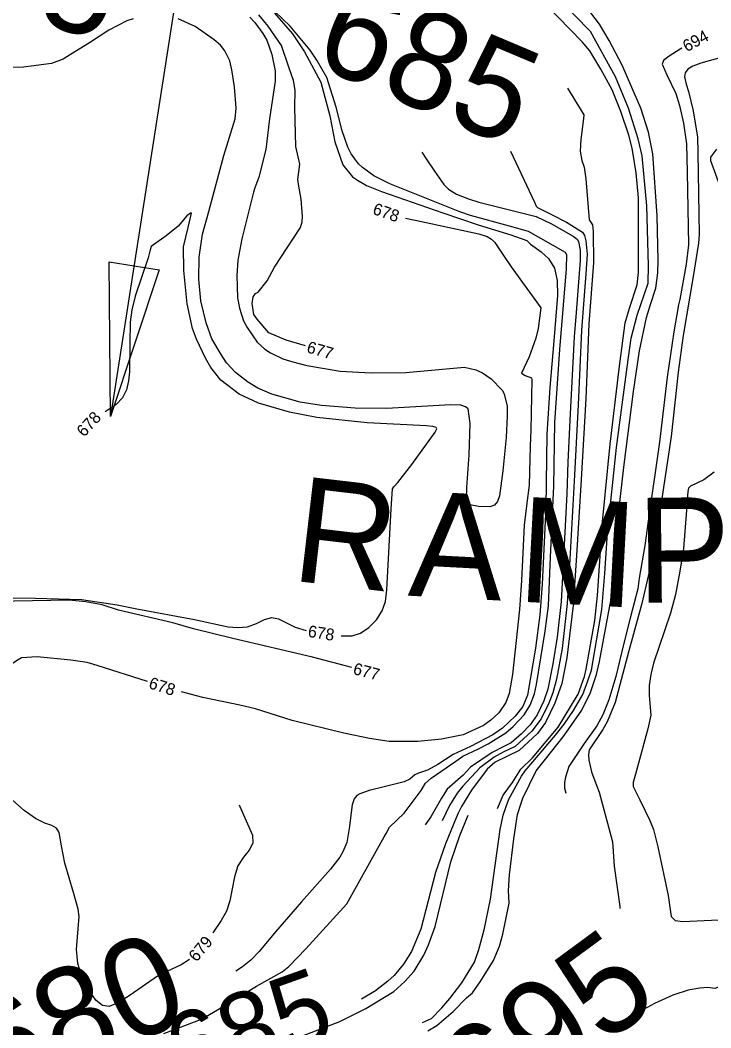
# Model space of a CAD drawing. Extents: x -291892836 to 2945206, y -477993085 to 1832792.
# Drawn here: x 1851493.5 to 1851727.1, y 544238.1 to 544578.8 of the extents above; entities that cross this region are included whole.
import ezdxf

# ---------------------------------------------------------------- set-up
doc = ezdxf.new("R2010")
doc.units = 0
for name, color, linetype in [('DT_X_Contour_Minor', 7, 'Continuous'), ('DT_X_Terrain_Ground_Line', 7, 'Continuous'), ('Level 19', 7, 'Continuous'), ('Level 40', 7, 'Continuous')]:
    doc.layers.add(name, color=color, linetype=linetype)

msp = doc.modelspace()

# ---------------------------------------------------------------- linework, layer by layer
at = {"layer": 'DT_X_Contour_Minor'}
for points in [[(1851531.68, 544579.29), (1851529.6, 544578.6), (1851523.46, 544575.49), (1851517, 544571.2), (1851510.54, 544567.23), (1851508.07, 544565.62), (1851504.12, 544564.17), (1851494.6, 544562.93), (1851490.63, 544562.85), (1851483.62, 544563.35), (1851477.39, 544564.65), (1851474.87, 544565.59), (1851472.41, 544566.76), (1851469.85, 544568.81), (1851466.75, 544571.69), (1851463.85, 544575.55), (1851462.39, 544578.37), (1851461, 544581.54), (1851456.81, 544594.48), (1851454.94, 544602.3), (1851452.23, 544617.54), (1851451.53, 544626.35), (1851451.1, 544641.26)], [(1851617.23, 544303.84), (1851618.4, 544305.96), (1851623.32, 544310.69), (1851629.13, 544318.42), (1851630.58, 544320.9), (1851632.5, 544322.48), (1851640.88, 544328.24), (1851643.22, 544329.96), (1851648.52, 544332.42), (1851651.73, 544334.17), (1851657.73, 544337.84), (1851660.25, 544340.04), (1851663.92, 544344), (1851665.98, 544347.19), (1851667.46, 544351.07), (1851668.1, 544354.21), (1851671.07, 544372.2), (1851672.12, 544380.82), (1851672.89, 544397.28), (1851673.94, 544421.24), (1851674.35, 544442.82), (1851676, 544467.43), (1851678.21, 544494.75), (1851678.38, 544499.48), (1851677.97, 544500.24), (1851665.44, 544507.33), (1851658.98, 544509.22), (1851645.75, 544512.78), (1851642.14, 544513.99), (1851618.52, 544523.49), (1851613.09, 544526.22), (1851609.27, 544529.01), (1851607.92, 544530.29), (1851605.47, 544533.58), (1851604.35, 544535.92), (1851602.37, 544541.41), (1851600.35, 544549.45), (1851597.19, 544559.47), (1851593.79, 544565.35), (1851591.56, 544568.67), (1851584.83, 544576.83), (1851574.41, 544586.83)], [(1851657.9, 544312.96), (1851658.81, 544315.45), (1851663.08, 544323.19), (1851664.28, 544325.01), (1851674.57, 544337.13), (1851677.49, 544340.83), (1851680.68, 544345.4), (1851683.77, 544350.83), (1851685.52, 544355.39), (1851686.66, 544359.01), (1851690.25, 544379.61), (1851691.17, 544391.79), (1851692.09, 544405.45), (1851695.17, 544434.29), (1851698.73, 544461.55), (1851700.17, 544471.32), (1851702.12, 544479.08), (1851705.84, 544489.86), (1851705.94, 544495.86), (1851705.37, 544516.06), (1851703.83, 544532.99), (1851702.48, 544538.7), (1851699.24, 544549.12), (1851694.85, 544559.67), (1851686.41, 544574.95), (1851675.39, 544586.26)], [(1851654.96, 544312.3), (1851656.82, 544316.8), (1851659.97, 544321.06), (1851662.8, 544325.53), (1851666.71, 544329.37), (1851675.44, 544339.78), (1851682.17, 544350.99), (1851684.32, 544356.88), (1851684.95, 544359.44), (1851687.83, 544375.83), (1851688.73, 544384.28), (1851690.47, 544409.19), (1851693, 544435.45), (1851696.02, 544460.97), (1851698.1, 544476.5), (1851699.57, 544481.42), (1851702.21, 544489.3), (1851702.6, 544493.49), (1851702.59, 544518.76), (1851701.84, 544527.19), (1851700.5, 544535.56), (1851699.39, 544539.89), (1851696.66, 544547.94), (1851693.69, 544555.28), (1851689.87, 544562.31), (1851686.17, 544568.5), (1851683.61, 544571.48), (1851671.39, 544584.03)], [(1851662.89, 544314.07), (1851663.44, 544315.8), (1851668.06, 544324.98), (1851671.2, 544329), (1851677.15, 544336.48), (1851679, 544339.22), (1851683.4, 544345.56), (1851686.33, 544351.53), (1851688.45, 544357.57), (1851689.43, 544362.02), (1851693.25, 544382.58), (1851693.94, 544391.7), (1851694.73, 544401.86), (1851697.69, 544427.67), (1851700.91, 544453.29), (1851702.97, 544467.04), (1851705.26, 544478.31), (1851706.66, 544482.7), (1851708.51, 544488.19), (1851709.13, 544493.38), (1851709.31, 544497.51), (1851708.95, 544512.69), (1851707.46, 544533.67), (1851705.99, 544540.94), (1851703.35, 544549.11), (1851700.41, 544556.05), (1851697.12, 544563.57), (1851692.72, 544571.93), (1851689.38, 544577.42), (1851685.36, 544582.82)], [(1851571.16, 544579.86), (1851572.9, 544578.01), (1851575.55, 544574.36), (1851576.92, 544572.06), (1851578.64, 544567.24), (1851579.78, 544561.69), (1851579.7, 544558.2), (1851577.85, 544545.41), (1851576.63, 544535.06), (1851574.24, 544525.76), (1851572.91, 544522.16), (1851572.43, 544520.71), (1851568.52, 544504.91), (1851567.18, 544497.67), (1851566.76, 544492.47), (1851567.02, 544484.96), (1851567.73, 544481.43), (1851569.03, 544477.2), (1851570.28, 544474.96), (1851573.69, 544469.98), (1851576.28, 544467.59), (1851578.22, 544466.39), (1851582.3, 544464.34), (1851585.67, 544463.25), (1851590.44, 544462.06), (1851601.7, 544460.15), (1851612.22, 544459.54), (1851623.94, 544459.74), (1851643.81, 544461.46), (1851647.58, 544460.64), (1851649.82, 544459.6), (1851652.8, 544457.55), (1851656.55, 544453.68), (1851657.18, 544452.52), (1851658.24, 544448.32), (1851658.25, 544444.98), (1851657.86, 544437.77), (1851656.77, 544426.42), (1851655.59, 544418), (1851654.98, 544416.07), (1851653.94, 544414.82), (1851652.33, 544414.27), (1851648.45, 544414.36), (1851645.55, 544414.91), (1851644.75, 544415.69), (1851644.41, 544417), (1851644.58, 544420.79), (1851645.32, 544431.82), (1851645.66, 544442.41), (1851645.01, 544447.38), (1851644.1, 544448.11), (1851642.57, 544448.7), (1851639.1, 544448.79), (1851617.38, 544447.51), (1851606.84, 544447.67), (1851595.38, 544448.58), (1851588.2, 544449.63), (1851578.58, 544452.33), (1851573.86, 544454.41), (1851570.35, 544456.59), (1851566.34, 544459.69), (1851563.3, 544463.02), (1851561.46, 544465.81), (1851558.35, 544471.13), (1851556.38, 544476.45), (1851554.66, 544483.89), (1851553.96, 544491.25), (1851554.1, 544498.71), (1851555.22, 544506.44), (1851557.3, 544514.16), (1851562.4, 544533.07), (1851566.24, 544545.45), (1851566.57, 544549.02), (1851565.97, 544556.25), (1851565.09, 544562.03), (1851564.45, 544565.09), (1851562.7, 544568.5), (1851561.27, 544570.39), (1851559.13, 544572.21), (1851552.69, 544576.64), (1851546.94, 544579.28)], [(1851589.99, 544468.69), (1851583.44, 544470.59), (1851577.6, 544473.15), (1851573.69, 544477.73), (1851572.48, 544479.31), (1851571.96, 544483.02), (1851572.34, 544485.25), (1851573.08, 544486.37), (1851574.04, 544486.81), (1851577, 544490.64), (1851579.55, 544495.33), (1851588.28, 544508.7), (1851588.91, 544510.66), (1851589.03, 544512.52), (1851588.59, 544518.25), (1851587.77, 544522.66), (1851587.37, 544524.94), (1851588.05, 544530.13), (1851586.72, 544536.09), (1851586.4, 544549.28), (1851586.54, 544555.18), (1851586, 544558.44), (1851584.45, 544562.58), (1851581.84, 544570.3), (1851577.39, 544576.81), (1851574.26, 544580.61)], [(1851579.49, 544581.23), (1851585.56, 544574.15), (1851589.62, 544568.13), (1851595.19, 544557.87), (1851598.27, 544546.45), (1851599.88, 544537.69), (1851602.67, 544529.94), (1851605.89, 544525.87), (1851607.56, 544524.69), (1851610.6, 544522.97), (1851615.66, 544520.86), (1851636.49, 544513.69), (1851648.39, 544509.66), (1851659.43, 544506.23), (1851664.85, 544504.3), (1851666.04, 544503.08), (1851669.68, 544500.52), (1851672.17, 544498.24), (1851674.15, 544495.01), (1851675.08, 544490.75), (1851675.17, 544485.74), (1851673.95, 544470.46), (1851672.62, 544454.65), (1851671.61, 544438.82), (1851671.25, 544414.2), (1851670.03, 544388.16), (1851669.28, 544377.74), (1851667.82, 544366.52), (1851665.05, 544350.62), (1851663.46, 544346.82), (1851660.93, 544343.51), (1851656.57, 544339.48), (1851653.38, 544337.19), (1851645.85, 544333.24), (1851639.96, 544330.57), (1851634.71, 544327.13), (1851631.21, 544325.22), (1851628.23, 544324.2), (1851627.03, 544323.65), (1851625.28, 544322.19), (1851623.39, 544321.31), (1851617.1, 544319.73), (1851611.48, 544318.42), (1851608.39, 544317.29), (1851607.31, 544316.66), (1851606.45, 544315.55), (1851605.77, 544313.48), (1851604.87, 544306.43)], [(1851717.29, 544569.33), (1851716.66, 544568.99), (1851712.96, 544566.71), (1851711.02, 544565.16), (1851710.59, 544563.95), (1851712.22, 544560.35), (1851715.25, 544554.08), (1851716.5, 544549.96), (1851717.79, 544543.96), (1851718.81, 544537.03), (1851719.09, 544527.48), (1851719.51, 544502.84), (1851718.72, 544496.33), (1851716.56, 544484.33), (1851716.08, 544482.63), (1851714.57, 544473.43), (1851712.25, 544458.16), (1851709.72, 544436.19), (1851705.85, 544409.41), (1851704.75, 544401.26), (1851702.8, 544390.15), (1851702.38, 544386.5), (1851699.89, 544377.05), (1851697.59, 544367.74), (1851694.91, 544356.89), (1851692.6, 544349), (1851690.56, 544344), (1851688.55, 544340.24), (1851684.26, 544334.31), (1851679.03, 544326.45), (1851677.95, 544322.91), (1851677.54, 544321.08), (1851677.64, 544319.1), (1851678, 544317.46)], [(1851731.3, 544566.47), (1851723.68, 544564.32), (1851720.99, 544563.27), (1851719.26, 544562.23), (1851718.36, 544561.05), (1851718.17, 544559.68), (1851718.75, 544557.2), (1851719.57, 544554.66), (1851721.11, 544548.13), (1851722.52, 544539.24), (1851722.72, 544533.95), (1851723.1, 544506.39), (1851722.93, 544503.4), (1851721.07, 544492.13), (1851717.76, 544472.24), (1851716.02, 544459.78), (1851713.6, 544438.03), (1851709.48, 544410.31), (1851707.97, 544400.12), (1851703.7, 544381.62), (1851699.38, 544365.61), (1851694.68, 544348.16), (1851691.97, 544341.54), (1851690.52, 544338.94), (1851685.94, 544332.08), (1851685.7, 544330.58), (1851685.81, 544328.64), (1851686.74, 544324.63), (1851688.55, 544319.82)], [(1851678.57, 544555.83), (1851684.07, 544546.83), (1851684.06, 544545.58), (1851683.12, 544538.48), (1851682.84, 544534.48), (1851683.47, 544531.43), (1851684.25, 544529.12), (1851684.79, 544525.19), (1851685.93, 544511.3), (1851687.08, 544509.63), (1851687.3, 544507.37), (1851687.41, 544496.83), (1851685.76, 544476.15), (1851684.82, 544450.74), (1851683.19, 544423.55), (1851681.64, 544397.85), (1851680.57, 544380.91), (1851678.43, 544363.26), (1851676.66, 544354.54), (1851674.32, 544347.93), (1851671.14, 544341.37), (1851668.4, 544337.59), (1851662.29, 544331.86), (1851654.15, 544327.89), (1851651.49, 544325.6), (1851646.14, 544318.49), (1851642.76, 544312.98), (1851641.61, 544310.74), (1851640.97, 544309.16)], [(1851629.35, 544534.19), (1851630.83, 544531.99), (1851633.61, 544527.82), (1851636.74, 544523.26), (1851638.39, 544521.69), (1851641.12, 544520.04), (1851645.11, 544518.37), (1851648.64, 544517.25), (1851667.96, 544512.44), (1851673.22, 544509.95), (1851680.47, 544505.76), (1851681.86, 544504.78), (1851682.34, 544503.94), (1851682.88, 544501.05), (1851682.91, 544497.52), (1851681.5, 544479.96), (1851680.88, 544471.79), (1851679.41, 544443.63), (1851678.74, 544429.35), (1851678.39, 544418.64), (1851677.01, 544392.71), (1851676.43, 544382.31), (1851675.11, 544370.2), (1851673.66, 544361.24), (1851671.96, 544352.64), (1851670.64, 544348.73), (1851668.34, 544343.9), (1851665.97, 544340.57), (1851662.99, 544337.53), (1851659.58, 544334.53), (1851657.06, 544333.23), (1851653.12, 544331.18), (1851645.85, 544326.21), (1851643.36, 544323.57), (1851637.93, 544318.84), (1851635.96, 544315.74), (1851632.39, 544309.42), (1851630.49, 544306.81)], [(1851659.31, 544534.49), (1851667.42, 544517.3), (1851668.04, 544515.9), (1851668.49, 544515.48), (1851673.45, 544513.02), (1851678.28, 544510.54), (1851683.72, 544507.12), (1851684.37, 544505.99), (1851684.82, 544504.25), (1851685.2, 544499.68), (1851684.82, 544493.04), (1851683.32, 544473.97), (1851682.2, 544448.76), (1851680.88, 544422.97), (1851679.28, 544394.54), (1851678.5, 544381.61), (1851676.75, 544366.39), (1851674.88, 544356.01), (1851673.63, 544351.44), (1851672.3, 544347.91), (1851669.72, 544342.6), (1851666.57, 544338.41), (1851660.93, 544333.2), (1851656.89, 544331.3), (1851653.82, 544329.68), (1851648.91, 544326.05), (1851643.26, 544319.84), (1851641.29, 544317.48), (1851638.75, 544313.24), (1851636.18, 544308.09)], [(1851728.98, 544535.24), (1851726.99, 544532.45), (1851726.97, 544531.41), (1851731.98, 544517.49)], [(1851602.06, 544370.69), (1851602.78, 544370.62), (1851605.8, 544370.7), (1851608.62, 544371.58), (1851611.44, 544373.48), (1851614.01, 544376.12), (1851615.96, 544379.11), (1851617.05, 544382.26), (1851617.54, 544386.17), (1851618.95, 544413.62), (1851619.48, 544420.36), (1851619.85, 544421.07), (1851621.19, 544422.48), (1851626.01, 544428.61), (1851633.83, 544439.47), (1851634.37, 544440.61), (1851634.21, 544441.06), (1851633.02, 544441.46), (1851630.95, 544441.62), (1851610.82, 544442.68), (1851593.86, 544444.51), (1851584.64, 544446.25), (1851574.1, 544449.36), (1851567.53, 544452.38), (1851561.34, 544457.06), (1851557.96, 544461.36), (1851556.21, 544464.52), (1851553.11, 544470.99), (1851551.8, 544474.54), (1851550, 544482.88), (1851548.82, 544494.16), (1851548.8, 544502.17), (1851550.31, 544508.77), (1851551.51, 544513.62), (1851551.13, 544513.62), (1851549.9, 544512.68), (1851546.93, 544509.19), (1851542.88, 544505.86), (1851537.86, 544502.32), (1851537.37, 544500.77), (1851536.82, 544498.49), (1851532.4, 544485.49), (1851531.26, 544480.87), (1851530.69, 544476.7), (1851530.61, 544469.54), (1851530.44, 544459.96), (1851530.16, 544456.83), (1851529.48, 544453.83), (1851528.15, 544451.13), (1851526, 544448.86), (1851522.26, 544446.4)], [(1851623.83, 544511.93), (1851629.18, 544510.76), (1851648.66, 544506.54), (1851651.43, 544505.65), (1851652.85, 544504.82), (1851654.02, 544503.69), (1851656.94, 544499.31), (1851659.6, 544495.38), (1851669.62, 544481.61), (1851668.68, 544474.6), (1851667.92, 544471.27), (1851665.61, 544464.99), (1851663.09, 544459.46), (1851664.26, 544458.69), (1851666.47, 544457.94), (1851666.56, 544457.25), (1851666.2, 544440.31), (1851665.93, 544434.79), (1851665.59, 544421.56), (1851664.82, 544415.52), (1851663.96, 544408.07), (1851663.04, 544389.34), (1851662.42, 544379.56), (1851660, 544357.56), (1851658.89, 544351.17), (1851657.74, 544348.13), (1851655.35, 544344.63), (1851652.64, 544342.19), (1851650.23, 544340.33), (1851643.29, 544337.2), (1851635.98, 544335.71), (1851627.94, 544334.93), (1851619.15, 544334.96), (1851618.25, 544334.94), (1851611.67, 544335.92), (1851602.95, 544337.77), (1851585.47, 544342.09), (1851573.06, 544346.01), (1851567.8, 544347.17), (1851555.24, 544349.86), (1851548.07, 544351.69)], [(1851728.17, 544425.99), (1851724.72, 544423.46), (1851720.22, 544421.25), (1851719.56, 544420.6), (1851719.3, 544419.43), (1851718.72, 544411.69), (1851717.84, 544400.22), (1851716.59, 544392.55), (1851715.1, 544384.61), (1851713.38, 544378.3), (1851707.65, 544361.47), (1851706.75, 544357.54), (1851706.24, 544353.83), (1851706.24, 544350.54), (1851706.76, 544343.88), (1851705.8, 544339.21), (1851702.61, 544327.61), (1851701.24, 544322.67)], [(1851459.47, 544352.17), (1851464.24, 544361.95), (1851466.96, 544365.45), (1851469.75, 544368.75), (1851471.46, 544370.71), (1851479.23, 544377.5), (1851482.11, 544379.77), (1851484.32, 544380.98), (1851490.1, 544383.49), (1851498.68, 544383.38), (1851514.27, 544382.91), (1851526.33, 544381.17), (1851532.96, 544379.78), (1851552.48, 544376.14), (1851563.87, 544373.74), (1851567.04, 544373.43), (1851570.37, 544373.73), (1851573.44, 544374.86), (1851576.19, 544376.2), (1851578.65, 544376.9), (1851580.91, 544376.39), (1851586.46, 544373.55), (1851590.19, 544372.47)], [(1851605.62, 544359.92), (1851592.4, 544363.46), (1851565.42, 544369.78), (1851552.14, 544373.02), (1851545.19, 544375.05), (1851526.73, 544379.38), (1851521.29, 544381.13), (1851515.76, 544382.18), (1851510.14, 544382.7), (1851491.44, 544382.41), (1851489.57, 544382.18), (1851486.94, 544381.28), (1851482.61, 544379.11), (1851480.27, 544377.42), (1851471.68, 544369.99), (1851468.55, 544366.2), (1851464.71, 544361.24), (1851462.93, 544357.75), (1851460.51, 544351.68)], [(1851536.59, 544355.18), (1851519.57, 544360.66), (1851516.15, 544361.63), (1851510.65, 544362.43), (1851499.31, 544363.57), (1851494, 544363.18), (1851492.24, 544362.26), (1851488.45, 544359.59), (1851484.76, 544355.46), (1851483.86, 544354.14), (1851479.54, 544346.35), (1851478.22, 544343.28)], [(1851921.73, 544337.9), (1851896.55, 544325.13), (1851881.69, 544318.35), (1851852.54, 544305.18), (1851826.96, 544293.37), (1851805.11, 544283.27), (1851791.14, 544277.36), (1851760.71, 544264.55), (1851745.48, 544258.17), (1851728.39, 544251.42), (1851726.02, 544251.75), (1851723.34, 544251.57), (1851719.38, 544250.83), (1851714.21, 544249.15), (1851708.05, 544246.31), (1851701.81, 544242.92), (1851692.99, 544237.39)], [(1851701.24, 544322.67), (1851700.83, 544321.22), (1851700.85, 544319.72), (1851703.04, 544315.23), (1851706.47, 544308.24), (1851707.64, 544305.14), (1851709.13, 544299.3), (1851712.69, 544282.91), (1851713.68, 544275.72), (1851715.02, 544274.44), (1851717.62, 544274.08), (1851729.7, 544274.65)], [(1851688.55, 544319.82), (1851689.29, 544317.84), (1851693.76, 544300.99), (1851694.35, 544292.79), (1851696.26, 544279.15), (1851696.24, 544278.5)], [(1851550.75, 544261.24), (1851548.01, 544259.37), (1851543.1, 544257.2), (1851540.29, 544255.78), (1851530.41, 544248.93), (1851526.51, 544246.56), (1851523.61, 544245.38), (1851521.39, 544245.62), (1851519.26, 544247.38), (1851516.84, 544250.67), (1851514.54, 544255.02), (1851512.99, 544259.84), (1851512.58, 544264.61), (1851513.49, 544275.71), (1851513.17, 544278.24), (1851511.54, 544283.86), (1851508.58, 544293.82), (1851507.46, 544299.63), (1851506.67, 544304.22), (1851505.79, 544305.68), (1851504.22, 544306.5), (1851501.89, 544307.3), (1851498.74, 544308.85), (1851494.89, 544311.65), (1851490.95, 544315.13)], [(1851567.61, 544313.47), (1851567.78, 544312.9), (1851572.14, 544303.29), (1851572.24, 544300.6), (1851571, 544298.22), (1851569.02, 544295.79), (1851567.13, 544292.86), (1851565.95, 544289.14), (1851564.45, 544281.01), (1851563.24, 544277.53), (1851561.54, 544274.37), (1851558.65, 544270.28)], [(1851629.52, 544239.89), (1851632.59, 544241.31), (1851636.07, 544244.92), (1851638.79, 544248.07), (1851642.87, 544253.35), (1851647.12, 544260.28), (1851648.66, 544264.66), (1851650.4, 544271.28), (1851652.6, 544281.6), (1851655.82, 544305.13), (1851656.83, 544310), (1851657.9, 544312.96)], [(1851631.38, 544237.16), (1851634.41, 544238.93), (1851639.94, 544243.65), (1851644.5, 544248.21), (1851646.45, 544249.96), (1851649.28, 544253.97), (1851653.63, 544260.89), (1851655.62, 544265.69), (1851656.73, 544269.77), (1851658.92, 544280.27), (1851658.62, 544284.61), (1851658.96, 544289.88), (1851660.49, 544302.06), (1851661.68, 544310.26), (1851662.89, 544314.07)], [(1851579.27, 544231.74), (1851601.56, 544240.31), (1851610.38, 544244.67), (1851619.92, 544250.43), (1851623.63, 544253.74), (1851626.79, 544257.3), (1851629.97, 544262.64), (1851631.57, 544266.13), (1851633.87, 544272.36), (1851639.1, 544294.23), (1851642.23, 544303.14), (1851645.04, 544310.07)], [(1851640.97, 544309.16), (1851637.37, 544300.37), (1851633.92, 544290.63), (1851629, 544271.48), (1851625.81, 544263.96), (1851623.17, 544259.7), (1851619.95, 544255.83), (1851617.89, 544253.89), (1851613.67, 544250.59), (1851608.91, 544247.79)], [(1851604.83, 544306.21), (1851603.99, 544300.79), (1851602.6, 544297.66), (1851601.58, 544295.86), (1851598.44, 544291.75), (1851588.69, 544280.69), (1851579.91, 544270.58), (1851574.3, 544263.92), (1851571.5, 544261.05), (1851568.76, 544258.78), (1851566.5, 544257.33)], [(1851604.87, 544306.43), (1851604.83, 544306.21)], [(1851542.15, 544236.15), (1851554.86, 544241.08), (1851560.26, 544244.2), (1851573.46, 544252.17), (1851582.11, 544257.04), (1851584.35, 544258.91), (1851590.09, 544264.83), (1851603.94, 544280.03), (1851616.6, 544302.69), (1851617.23, 544303.84)]]:
    msp.add_lwpolyline(points, dxfattribs=at)
at = {"layer": 'Level 40'}
for p, q in [((1851666.59, 545359.82), (1851524.12, 544444.79)), ((1851524.12, 544444.79), (1851523.58, 544497.07)), ((1851523.58, 544497.07), (1851540.55, 544494.43)), ((1851540.55, 544494.43), (1851524.12, 544444.79))]:
    msp.add_line(p, q, dxfattribs=at)

# ---------------------------------------------------------------- texts
at = {"layer": 'DT_X_Terrain_Ground_Line'}
for s, height, rotation, p in [('675', 33, 341.7808, (1851451.35, 544594.26)), ('685', 33, 337.094, (1851591.43, 544564.32)), ('680', 33, 22.9126, (1851484.39, 544212.9)), ('695', 33, 36.3484, (1851651.31, 544203.09)), ('685', 25, 19.641, (1851548.52, 544216.82))]:
    msp.add_text(s, height=height, rotation=rotation, dxfattribs=at).set_placement(p)
at = {"layer": 'Level 19'}
for s, rotation, p in [('694', 28.4645, (1851718.93, 544567.95)), ('678', 340.8927, (1851612.44, 544513.39)), ('677', 343.8033, (1851590.14, 544466.56)), ('678', 47.2805, (1851515.15, 544437.67)), ('678', 350.971, (1851590.62, 544370.34)), ('677', 345.0352, (1851605.82, 544357.8)), ('678', 342.1417, (1851536.7, 544353.05)), ('679', 50.2484, (1851553.18, 544260.18))]:
    msp.add_text(s, height=4, rotation=rotation, dxfattribs=at).set_placement(p)
at = {"layer": 'Level 40'}
for s, rotation, p in [('R', 353.3366, (1851584.71, 544389.42)), ('A', 356.9599, (1851624.46, 544384.25)), ('M', 356.9599, (1851661.31, 544382.29)), ('P', 0.5833, (1851702.19, 544381.78))]:
    msp.add_text(s, height=35.5, rotation=rotation, dxfattribs=at).set_placement(p)

doc.saveas('drawing.dxf')
